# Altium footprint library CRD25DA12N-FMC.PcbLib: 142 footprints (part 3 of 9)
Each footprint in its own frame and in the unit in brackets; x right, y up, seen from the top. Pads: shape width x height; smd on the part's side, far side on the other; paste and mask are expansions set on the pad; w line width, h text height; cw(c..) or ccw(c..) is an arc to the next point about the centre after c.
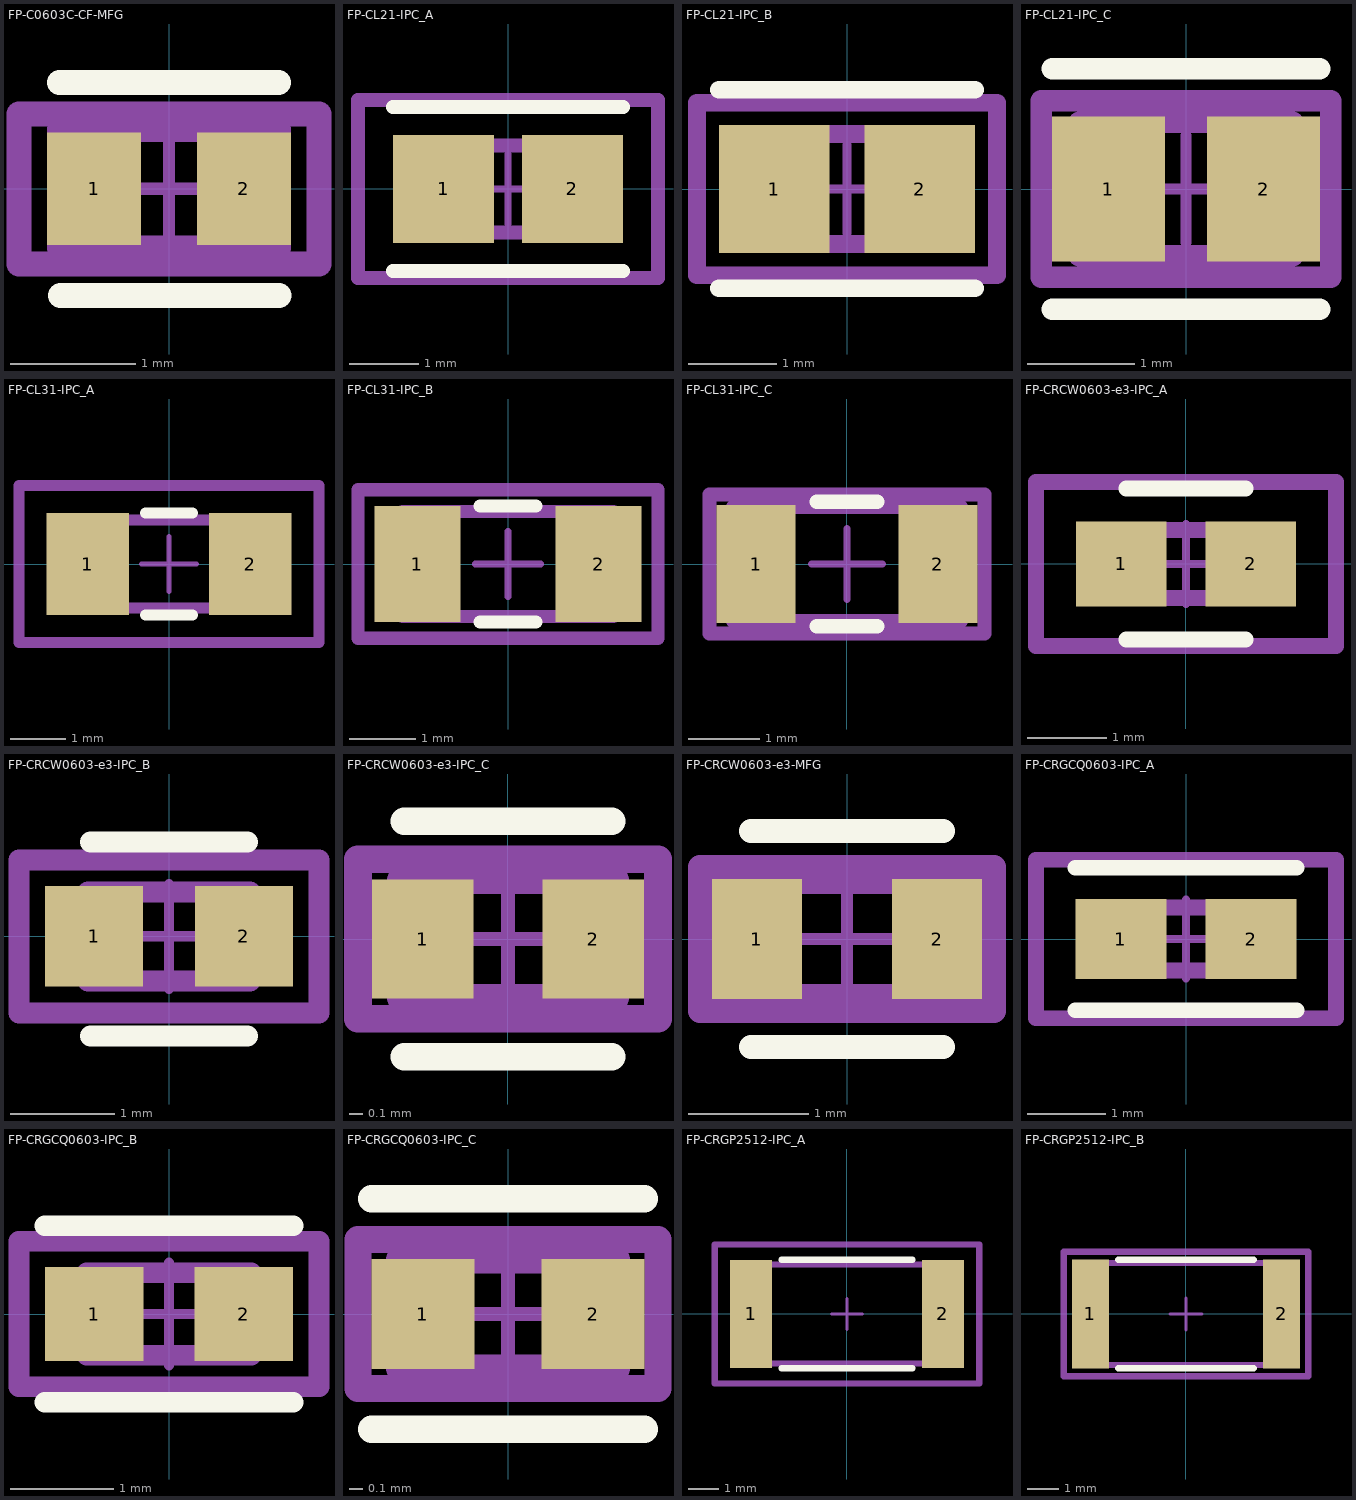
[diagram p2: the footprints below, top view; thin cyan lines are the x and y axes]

## FP-C0603C-CF-MFG [mm]
pads (2):
  rect 0.75x0.9 smd paste+0 mask+0: 1(-0.6,0) 2(0.6,0)
Top Overlay:
  lines w0.2: -0.875,0.85 0.875,0.85 ; -0.87,-0.853 0.88,-0.853
Mechanical 5:
  lines w0.2: -1.2,-0.6 1.2,-0.6 1.2,0.6 -1.2,0.6 -1.2,-0.6
  text ".Designator" at 0,0.188 h1
Mechanical 13:
  lines w0.2: -0.875,-0.475 0.875,-0.475 0.875,0.475 -0.875,0.475 -0.875,-0.475
Mechanical 15:
  lines w0.2: -1.2,-0.6 1.2,-0.6 1.2,0.6 -1.2,0.6 -1.2,-0.6
Mechanical 16:
  lines w0.1: -0.5,0 0.5,0 ; 0,-0.5 0,0.5
3D body "Cap_KEMET_C0603C272M5JACTU_eec.STEP": height 0.25, standoff 0, extent -1.2,-0.6 1.2,0.6

## FP-CL21-IPC_A [mm]
pads (2):
  rect 1.455x1.556 smd paste+0 mask+0: 1(-0.926,0) 2(0.926,0)
Top Overlay:
  lines w0.2: -1.653,-1.178 1.653,-1.178 ; -1.653,1.178 1.653,1.178
Mechanical 5:
  lines w0.2: -2.153,-1.278 -2.153,1.278 2.153,1.278 2.153,-1.278 -2.153,-1.278
  text ".Designator" at 0,0.188 h1
Mechanical 13:
  lines w0.2: -1,-0.625 -1,0.625 1,0.625 1,-0.625 -1,-0.625
Mechanical 15:
  lines w0.2: -2.153,-1.278 -2.153,1.278 2.153,1.278 2.153,-1.278 -2.153,-1.278
Mechanical 16:
  lines w0.1: -0.5,0 0.5,0 ; 0,-0.5 0,0.5
3D body "Cap_Samsung_CL21B273KBANNNC_eec.STEP": height 0.25, standoff 0, extent -2.153,-1.278 2.153,1.278

## FP-CL21-IPC_B [mm]
pads (2):
  rect 1.255x1.456 smd paste+0 mask+0: 1(-0.826,0) 2(0.826,0)
Top Overlay:
  lines w0.2: -1.453,-1.128 1.453,-1.128 ; -1.453,1.128 1.453,1.128
Mechanical 5:
  lines w0.2: -1.703,-0.978 -1.703,0.978 1.703,0.978 1.703,-0.978 -1.703,-0.978
  text ".Designator" at 0,0.188 h1
Mechanical 13:
  lines w0.2: -1,-0.625 -1,0.625 1,0.625 1,-0.625 -1,-0.625
Mechanical 15:
  lines w0.2: -1.703,-0.978 -1.703,0.978 1.703,0.978 1.703,-0.978 -1.703,-0.978
Mechanical 16:
  lines w0.1: -0.5,0 0.5,0 ; 0,-0.5 0,0.5
3D body "Cap_Samsung_CL21B273KBANNNC_eec.STEP": height 0.25, standoff 0, extent -1.703,-0.978 1.703,0.978

## FP-CL21-IPC_C [mm]
pads (2):
  rect 1.055x1.356 smd paste+0 mask+0: 1(-0.726,0) 2(0.726,0)
Top Overlay:
  lines w0.2: -1.253,-1.125 1.253,-1.125 ; -1.253,1.125 1.253,1.125
Mechanical 5:
  lines w0.2: -1.353,-0.825 -1.353,0.825 1.353,0.825 1.353,-0.825 -1.353,-0.825
  text ".Designator" at 0,0.188 h1
Mechanical 13:
  lines w0.2: -1,-0.625 -1,0.625 1,0.625 1,-0.625 -1,-0.625
Mechanical 15:
  lines w0.2: -1.353,-0.825 -1.353,0.825 1.353,0.825 1.353,-0.825 -1.353,-0.825
Mechanical 16:
  lines w0.1: -0.5,0 0.5,0 ; 0,-0.5 0,0.5
3D body "Cap_Samsung_CL21B273KBANNNC_eec.STEP": height 0.25, standoff 0, extent -1.353,-0.825 1.353,0.825

## FP-CL31-IPC_A [mm]
pads (2):
  rect 1.505x1.858 smd paste+0 mask+0: 1(-1.476,0) 2(1.476,0)
Top Overlay:
  lines w0.2: -0.424,-0.929 0.424,-0.929 ; -0.424,0.929 0.424,0.929
Mechanical 5:
  lines w0.2: -2.729,-1.429 -2.729,1.429 2.729,1.429 2.729,-1.429 -2.729,-1.429
  text ".Designator" at 0,0.188 h1
Mechanical 13:
  lines w0.2: -1.6,-0.8 -1.6,0.8 1.6,0.8 1.6,-0.8 -1.6,-0.8
Mechanical 15:
  lines w0.2: -2.729,-1.429 -2.729,1.429 2.729,1.429 2.729,-1.429 -2.729,-1.429
Mechanical 16:
  lines w0.1: -0.5,0 0.5,0 ; 0,-0.5 0,0.5
3D body "Cap_Samsung_CL31B105KOFNNNE_eec.STEP": height 0.25, standoff 0, extent -2.729,-1.429 2.729,1.429

## FP-CL31-IPC_B [mm]
pads (2):
  rect 1.305x1.758 smd paste+0 mask+0: 1(-1.376,0) 2(1.376,0)
Top Overlay:
  lines w0.2: -0.424,-0.879 0.424,-0.879 ; -0.424,0.879 0.424,0.879
Mechanical 5:
  lines w0.2: -2.279,-1.129 -2.279,1.129 2.279,1.129 2.279,-1.129 -2.279,-1.129
  text ".Designator" at 0,0.188 h1
Mechanical 13:
  lines w0.2: -1.6,-0.8 -1.6,0.8 1.6,0.8 1.6,-0.8 -1.6,-0.8
Mechanical 15:
  lines w0.2: -2.279,-1.129 -2.279,1.129 2.279,1.129 2.279,-1.129 -2.279,-1.129
Mechanical 16:
  lines w0.1: -0.5,0 0.5,0 ; 0,-0.5 0,0.5
3D body "Cap_Samsung_CL31B105KOFNNNE_eec.STEP": height 0.25, standoff 0, extent -2.279,-1.129 2.279,1.129

## FP-CL31-IPC_C [mm]
pads (2):
  rect 1.105x1.658 smd paste+0 mask+0: 1(-1.276,0) 2(1.276,0)
Top Overlay:
  lines w0.2: -0.424,-0.875 0.424,-0.875 ; -0.424,0.875 0.424,0.875
Mechanical 5:
  lines w0.2: -1.929,-0.975 -1.929,0.975 1.929,0.975 1.929,-0.975 -1.929,-0.975
  text ".Designator" at 0,0.188 h1
Mechanical 13:
  lines w0.2: -1.6,-0.8 -1.6,0.8 1.6,0.8 1.6,-0.8 -1.6,-0.8
Mechanical 15:
  lines w0.2: -1.929,-0.975 -1.929,0.975 1.929,0.975 1.929,-0.975 -1.929,-0.975
Mechanical 16:
  lines w0.1: -0.5,0 0.5,0 ; 0,-0.5 0,0.5
3D body "Cap_Samsung_CL31B105KOFNNNE_eec.STEP": height 0.25, standoff 0, extent -1.929,-0.975 1.929,0.975

## FP-CRCW0603-e3-IPC_A [mm]
pads (2):
  rect 1.135x1.062 smd paste+0 mask+0: 1(-0.815,0) 2(0.815,0)
Top Overlay:
  lines w0.2: -0.75,-0.95 0.75,-0.95 ; -0.75,0.95 0.75,0.95
Mechanical 5:
  lines w0.2: -1.883,-1.031 1.883,-1.031 1.883,1.031 -1.883,1.031 -1.883,-1.031
  text ".Designator" at 0,0.188 h1
Mechanical 13:
  lines w0.2: -0.775,-0.425 0.775,-0.425 0.775,0.425 -0.775,0.425 -0.775,-0.425
Mechanical 15:
  lines w0.2: -1.883,-1.031 1.883,-1.031 1.883,1.031 -1.883,1.031 -1.883,-1.031
Mechanical 16:
  lines w0.1: -0.5,0 0.5,0 ; 0,-0.5 0,0.5
3D body "Res_Vishay_CRCW06033M90FKEC_eec.STEP": height 0.25, standoff 0, extent -1.883,-1.031 1.883,1.031

## FP-CRCW0603-e3-IPC_B [mm]
pads (2):
  rect 0.935x0.962 smd paste+0 mask+0: 1(-0.715,0) 2(0.715,0)
Top Overlay:
  lines w0.2: -0.75,-0.95 0.75,-0.95 ; -0.75,0.9 0.75,0.9
Mechanical 5:
  lines w0.2: -1.433,-0.731 -1.433,0.731 1.433,0.731 1.433,-0.731 -1.433,-0.731
  text ".Designator" at 0,0.188 h1
Mechanical 13:
  lines w0.2: -0.775,-0.425 -0.775,0.425 0.775,0.425 0.775,-0.425 -0.775,-0.425
Mechanical 15:
  lines w0.2: -1.433,-0.731 -1.433,0.731 1.433,0.731 1.433,-0.731 -1.433,-0.731
Mechanical 16:
  lines w0.1: -0.5,0 0.5,0 ; 0,-0.5 0,0.5
3D body "Res_Vishay_CRCW06033M90FKEC_eec.STEP": height 0.25, standoff 0, extent -1.433,-0.731 1.433,0.731

## FP-CRCW0603-e3-IPC_C [mm]
pads (2):
  rect 0.735x0.862 smd paste+0 mask+0: 1(-0.615,0) 2(0.615,0)
Top Overlay:
  lines w0.2: -0.75,-0.85 0.75,-0.85 ; -0.75,0.85 0.75,0.85
Mechanical 5:
  lines w0.2: -1.083,-0.575 1.083,-0.575 1.083,0.575 -1.083,0.575 -1.083,-0.575
  text ".Designator" at 0,0.188 h1
Mechanical 13:
  lines w0.2: -0.775,-0.425 0.775,-0.425 0.775,0.425 -0.775,0.425 -0.775,-0.425
Mechanical 15:
  lines w0.2: -1.083,-0.575 1.083,-0.575 1.083,0.575 -1.083,0.575 -1.083,-0.575
Mechanical 16:
  lines w0.1: -0.5,0 0.5,0 ; 0,-0.5 0,0.5
3D body "Res_Vishay_CRCW06033M90FKEC_eec.STEP": height 0.25, standoff 0, extent -1.083,-0.575 1.083,0.575

## FP-CRCW0603-e3-MFG [mm]
pads (2):
  rect 0.75x1 smd paste+0 mask+0: 1(-0.75,0) 2(0.75,0)
Top Overlay:
  lines w0.2: -0.8,-0.9 0.8,-0.9 ; -0.8,0.9 0.8,0.9
Mechanical 5:
  lines w0.2: -1.225,-0.6 1.225,-0.6 1.225,0.6 -1.225,0.6 -1.225,-0.6
  text ".Designator" at 0,0.188 h1
Mechanical 13:
  lines w0.2: -0.825,-0.475 0.825,-0.475 0.825,0.475 -0.825,0.475 -0.825,-0.475
Mechanical 15:
  lines w0.2: -1.225,-0.6 1.225,-0.6 1.225,0.6 -1.225,0.6 -1.225,-0.6
Mechanical 16:
  lines w0.1: -0.5,0 0.5,0 ; 0,-0.5 0,0.5
3D body "Res_Vishay_CRCW06033M90FKEC_eec.STEP": height 0.25, standoff 0, extent -1.225,-0.6 1.225,0.6

## FP-CRGCQ0603-IPC_A [mm]
pads (2):
  rect 1.158x1.012 smd paste+0 mask+0: 1(-0.827,0) 2(0.827,0)
Top Overlay:
  lines w0.2: -1.406,-0.906 1.406,-0.906 ; -1.406,0.906 1.406,0.906
Mechanical 5:
  lines w0.2: -1.906,-1.006 -1.906,1.006 1.906,1.006 1.906,-1.006 -1.906,-1.006
  text ".Designator" at 0,0.188 h1
Mechanical 13:
  lines w0.2: -0.8,-0.4 -0.8,0.4 0.8,0.4 0.8,-0.4 -0.8,-0.4
Mechanical 15:
  lines w0.2: -1.906,-1.006 -1.906,1.006 1.906,1.006 1.906,-1.006 -1.906,-1.006
Mechanical 16:
  lines w0.1: -0.5,0 0.5,0 ; 0,-0.5 0,0.5
3D body "Res_TE_Connectivity_CRGCQ0603F12R_eec.STEP": height 0.25, standoff 0, extent -1.906,-1.006 1.906,1.006

## FP-CRGCQ0603-IPC_B [mm]
pads (2):
  rect 0.958x0.912 smd paste+0 mask+0: 1(-0.727,0) 2(0.727,0)
Top Overlay:
  lines w0.2: -1.206,-0.856 1.206,-0.856 ; -1.206,0.856 1.206,0.856
Mechanical 5:
  lines w0.2: -1.456,-0.706 -1.456,0.706 1.456,0.706 1.456,-0.706 -1.456,-0.706
  text ".Designator" at 0,0.188 h1
Mechanical 13:
  lines w0.2: -0.8,-0.4 -0.8,0.4 0.8,0.4 0.8,-0.4 -0.8,-0.4
Mechanical 15:
  lines w0.2: -1.456,-0.706 -1.456,0.706 1.456,0.706 1.456,-0.706 -1.456,-0.706
Mechanical 16:
  lines w0.1: -0.5,0 0.5,0 ; 0,-0.5 0,0.5
3D body "Res_TE_Connectivity_CRGCQ0603F12R_eec.STEP": height 0.25, standoff 0, extent -1.456,-0.706 1.456,0.706

## FP-CRGCQ0603-IPC_C [mm]
pads (2):
  rect 0.758x0.812 smd paste+0 mask+0: 1(-0.627,0) 2(0.627,0)
Top Overlay:
  lines w0.2: -1.006,-0.85 1.006,-0.85 ; -1.006,0.85 1.006,0.85
Mechanical 5:
  lines w0.2: -1.106,-0.55 -1.106,0.55 1.106,0.55 1.106,-0.55 -1.106,-0.55
  text ".Designator" at 0,0.188 h1
Mechanical 13:
  lines w0.2: -0.8,-0.4 -0.8,0.4 0.8,0.4 0.8,-0.4 -0.8,-0.4
Mechanical 15:
  lines w0.2: -1.106,-0.55 -1.106,0.55 1.106,0.55 1.106,-0.55 -1.106,-0.55
Mechanical 16:
  lines w0.1: -0.5,0 0.5,0 ; 0,-0.5 0,0.5
3D body "Res_TE_Connectivity_CRGCQ0603F12R_eec.STEP": height 0.25, standoff 0, extent -1.106,-0.55 1.106,0.55

## FP-CRGP2512-IPC_A [mm]
pads (2):
  rect 1.358x3.506 smd paste+0 mask+0: 1(-3.102,0) 2(3.102,0)
Top Overlay:
  lines w0.2: -2.123,-1.753 2.123,-1.753 ; -2.123,1.753 2.123,1.753
Mechanical 5:
  lines w0.2: -4.281,-2.253 -4.281,2.253 4.281,2.253 4.281,-2.253 -4.281,-2.253
  text ".Designator" at 0,0.188 h1
Mechanical 13:
  lines w0.2: -3.175,-1.6 -3.175,1.6 3.175,1.6 3.175,-1.6 -3.175,-1.6
Mechanical 15:
  lines w0.2: -4.281,-2.253 -4.281,2.253 4.281,2.253 4.281,-2.253 -4.281,-2.253
Mechanical 16:
  lines w0.1: -0.5,0 0.5,0 ; 0,-0.5 0,0.5
3D body "Res_TE_CRGP2512F47R_eec.STEP": height 0.25, standoff 0, extent -4.281,-2.253 4.281,2.253

## FP-CRGP2512-IPC_B [mm]
pads (2):
  rect 1.158x3.406 smd paste+0 mask+0: 1(-3.002,0) 2(3.002,0)
Top Overlay:
  lines w0.2: -2.123,-1.703 2.123,-1.703 ; -2.123,1.703 2.123,1.703
Mechanical 5:
  lines w0.2: -3.831,-1.953 3.831,-1.953 3.831,1.953 -3.831,1.953 -3.831,-1.953
  text ".Designator" at 0,0.188 h1
Mechanical 13:
  lines w0.2: -3.175,-1.6 3.175,-1.6 3.175,1.6 -3.175,1.6 -3.175,-1.6
Mechanical 15:
  lines w0.2: -3.831,-1.953 3.831,-1.953 3.831,1.953 -3.831,1.953 -3.831,-1.953
Mechanical 16:
  lines w0.1: -0.5,0 0.5,0 ; 0,-0.5 0,0.5
3D body "Res_TE_CRGP2512F47R_eec.STEP": height 0.25, standoff 0, extent -3.831,-1.953 3.831,1.953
